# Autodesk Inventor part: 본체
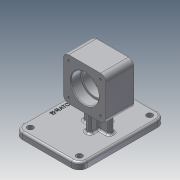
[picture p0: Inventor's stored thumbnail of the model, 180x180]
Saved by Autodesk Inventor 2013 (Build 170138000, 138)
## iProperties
Created: 2020-11
Part Number: 본체
Material: 알루미늄 6061
Document SubType Name: Modeling
Designer: 00
Density: 2.71 g/cm^3
Mass: 685.745 g
Surface Area: 542.794 cm^2
Volume: 253.042 cm^3
Author: 00
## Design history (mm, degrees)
sketch "스케치1"
  geometry: L1 (-24, 32)-(24, 32); L2 (32, 24)-(32, -24); L3 (24, -32)-(-24, -32); L4 (-32, -24)-(-32, 24); L5 (-32, 32)-(32, -32); L6 (32, 32)-(-32, -32); A1 r 8 centre (-24, 24) between (-24, 32) and (-32, 24); A2 r 8 centre (24, 24) between (32, 24) and (24, 32); A3 r 8 centre (24, -24) between (24, -32) and (32, -24); A4 r 8 centre (-24, -24) between (-32, -24) and (-24, -32); 1 further point
  constraints: 12 end point, 8 point on circle, 8 point on line, 8 tangent, 4 centre point, 3 equal radius, 2 midpoint, 2 parallel, 1 horizontal, 1 perpendicular
  dimensions: "d0" = 64 distance of L5.end L6.end; "d1" = 64 distance of L6.start L5.end; "d2" = 8 radius of A1
extrude "돌출1" new body sketch "스케치1" stored distance "d3" = 42; taper "d4" = 0 deg
sketch "스케치3"
  geometry: L1 (32, -21)-(-32, -21) reference; L2 (-32, -21)-(-32, 21) reference; L3 (-32, 21)-(32, 21) reference; L4 (32, 21)-(32, -21) reference; L5 (0, 21)-(0, -21); L6 (0, 21)-(21, 21); L7 (21, 21)-(21, 6); L8 (21, 6)-(18, 6); L9 (18, 6)-(18, -6); L10 (18, -6)-(21, -6); L11 (21, -6)-(21, -21); L12 (21, -21)-(0, -21); 1 further point
  constraints: 16 end point, 3 perpendicular, 2 midpoint, 2 parallel, 2 point on line, 1 collinear
  dimensions: "d11" = 15 distance of L6.end L7.end; "d13" = 15 distance of L10.end L11.end; "d14" = 42 diameter of L7 L5; "d15" = 42 diameter of L11 L5; "d16" = 36 diameter of L9 L5
revolve "회전1" sketch "스케치3" stored, may be unused: angle "d17" = 90 deg
node "작업 평면1"
sketch "스케치4"
  geometry: L1 (24, -21)-(-24, -21) reference; L2 (32, 21)-(32, -21) reference; L3 (-24, 21)-(24, 21) reference; L4 (-32, -21)-(-32, 21) reference; L5 (62, -65)-(-36, -65); L6 (-36, -65)-(-36, 65); L7 (-36, 65)-(62, 65); L8 (62, 65)-(62, -65); L9 (62, -65)-(-36, 65); L10 (-36, -65)-(62, 65); 2 further points
  constraints: 12 end point, 2 midpoint, 2 parallel, 1 horizontal, 1 perpendicular
  dimensions: "d19" = 98 distance of L6.end L7.end; "d20" = 130 distance of L5.end L6.end; "d21" = 65 distance from line of point (0, 0) L5; "d59" = 62 distance from line of point (0, 0) L8
extrude "돌출2" join sketch "스케치4" distance "d23" = 10; taper "d24" = 0 deg
fillet "모깎기1" dims "d25" = 12
sketch "스케치5"
  geometry: L1 (-20, 4)-(20, 4); L2 (20, 4)-(20, -4); L3 (20, -4)-(-20, -4); L4 (-20, -4)-(-20, 4); L5 (-20, 4)-(20, -4); L6 (20, 4)-(-20, -4); L7 (-4, 17)-(4, 17); L8 (4, 17)-(4, -17); L9 (4, -17)-(-4, -17); L10 (-4, -17)-(-4, 17); L11 (-4, 17)-(4, -17); L12 (4, 17)-(-4, -17); L13 (36, 53)-(36, -53) reference; L14 (24, -65)-(-50, -65) reference; L15 (-62, -53)-(-62, 53) reference; L16 (-50, 65)-(24, 65) reference; A1 r 12 centre (24, 53) between (36, 53) and (24, 65) reference; A2 r 12 centre (24, -53) between (24, -65) and (36, -53) reference; A3 r 12 centre (-50, -53) between (-62, -53) and (-50, -65) reference; A4 r 12 centre (-50, 53) between (-50, 65) and (-62, 53) reference; 5 further points
  constraints: 24 end point, 7 midpoint, 4 parallel, 2 horizontal, 2 perpendicular, 1 coincident
  dimensions: "d26" = 8 distance of L1.end L2.end; "d28" = 40 distance of L1.start L1.end; "d29" = 8 distance of L7.start L7.end; "d30" = 34 distance of L9.end L7.start
extrude "돌출3" join sketch "스케치5" stored distance "d31" = 0; taper "d32" = 0 deg
sketch "스케치6"
  geometry: A1 r 8 centre (-24, -24) between (-32, -24) and (-24, -32) reference; A2 r 8 centre (24, -24) between (24, -32) and (32, -24) reference; A3 r 8 centre (24, 24) between (32, 24) and (24, 32) reference; A4 r 8 centre (-24, 24) between (-24, 32) and (-32, 24) reference; 4 further points
  constraints: 4 coincident
hole "구멍1" sketch "스케치6" at (-24, 24), (24, 24), (24, -24), (-24, -24) diameter "d33" = 3.242; stored, may be unused: countersink angle "d37" = 90 deg, drill point angle "d39" = 118 deg; dims "d34" = 8, "d35" = 4, "d36" = 2, "d38" = 10
sketch "스케치8"
  geometry: A1 r 12 centre (-50, 53) between (-50, 65) and (-62, 53) reference; A2 r 12 centre (-50, -53) between (-62, -53) and (-50, -65) reference; A3 r 12 centre (24, -53) between (24, -65) and (36, -53) reference; A4 r 12 centre (24, 53) between (36, 53) and (24, 65) reference; 5 further points
  constraints: 4 coincident
hole "구멍2" sketch "스케치8" at (-50, 53), (-50, -53), (24, -53), (24, 53) diameter "d44" = 9; stored, may be unused: countersink angle "d48" = 90 deg, drill point angle "d50" = 118 deg; dims "d45" = 8, "d46" = 4, "d47" = 2, "d49" = 10
fillet "모깎기2" dims "d51" = 3
fillet "모깎기3" dims "d52" = 3
fillet "모깎기4" dims "d53" = 3
fillet "모깎기5" dims "d54" = 3
chamfer "모따기1" distance "d55" = 1; stored, may be unused: second distance "d56" = 2, angle "d57" = 45 deg
fillet "모깎기6" dims "d58" = 0.3
sketch "스케치9"
  geometry: L1 (-62, 53)-(-62, -53) reference; L2 (24, 65)-(-50, 65) reference; 2 further points
  constraints: 1 other
  dimensions: "d62" = 10 distance from line of point (-52, 0) L1; "d63" = 65 distance from line of L2 point (-52, 0)
feature "엠보싱2" sketch "스케치9" dims "d11" = 15, "d13" = 15, "d14" = 42, "d15" = 42, "d16" = 36, "d64" = 0.5, "d65" = 0
node "솔리드1"
mirror "대칭1"
node "절단 모서리 투영1"
node "절단 모서리 투영2"
